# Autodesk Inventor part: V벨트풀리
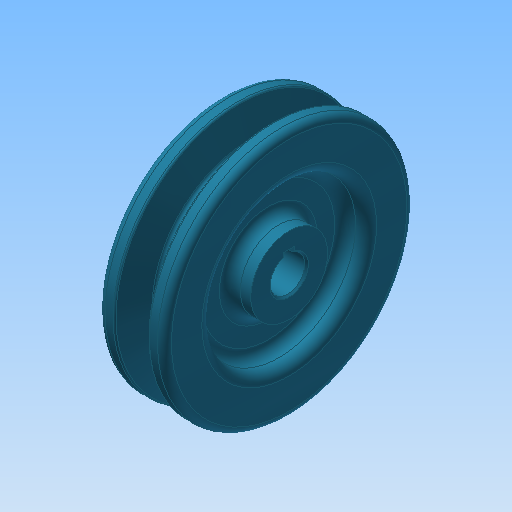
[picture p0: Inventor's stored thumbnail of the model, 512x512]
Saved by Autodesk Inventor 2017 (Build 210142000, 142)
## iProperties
Created: 2015-11
Part Number: V벨트풀리
Material: 강철, 탄소
Document SubType Name: Modeling
Designer: mduedu
Density: 7.87 g/cm^3
Mass: 380.065 g
Surface Area: 160.69 cm^2
Volume: 48.2929 cm^3
Appearance: 터키옥색
Author: mduedu
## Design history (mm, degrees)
sketch "스케치1"
  geometry: L1 (-9.5, 0)-(9.5, 0); L2 (0, 0)-(0, 35.7); L3 (-4.825, 35.7)-(-9.5, 35.7); L4 (-9.5, 35.7)-(-9.5, 0); L5 (0, 26.7)-(-2.074, 26.7); L6 (-2.074, 26.7)-(-4.825, 35.7); L7 (4.825, 35.7)-(9.5, 35.7); L8 (9.5, 35.7)-(9.5, 0); L9 (0, 26.7)-(2.074, 26.7); L10 (2.074, 26.7)-(4.825, 35.7); L11 (-9.5, 33)-(9.5, 33); 3 further points
  constraints: 22 end point, 7 point on line, 4 perpendicular, 3 symmetric about line, 1 coincident, 1 horizontal, 1 horizontal alignment, 1 midpoint, 1 vertical
  dimensions: "d0" = 19 distance of L1.start L1.end; "d2" = 71.4 diameter of L2.end L1 (derived); "d3" = 34 deg angle of L10 L6; "d4" = 6.3 distance between parallel lines of L11 L9; "d5" = 2.7 distance between parallel lines of L7 L11; "d6" = 8 distance of point (4, 33) point (-4, 33); "d7" = 66 diameter of L11 L1
revolve "회전1" sketch "스케치1" stored, may be unused: angle "d8" = 90 deg
sketch "스케치2"
  geometry: C1 r 22 at (0, 0); C2 r 11 at (0, 0); 1 further point
  constraints: 2 centre point, 2 coincident
  dimensions: "d9" = 44 diameter of C1; "d10" = 22 diameter of C2
extrude "돌출1" cut sketch "스케치2" distance "d11" = 6; taper "d12" = 0 deg
fillet "모깎기1" dims "d13" = 3
fillet "모깎기2" dims "d14" = 3
fillet "모깎기3" dims "d15" = 1, "d16" = 0.5, "d17" = 2
hole "구멍1" diameter "d20" = 10; stored, may be unused: countersink angle "d24" = 90 deg, drill point angle "d26" = 118 deg; dims "d18" = 10, "d19" = 10, "d21" = 6, "d22" = 4, "d23" = 2, "d25" = 8
sketch "스케치3"
  geometry: L1 (-1.5, 0)-(1.5, 0); L2 (1.5, 0)-(1.5, 6.4); L3 (1.5, 6.4)-(-1.5, 6.4); L4 (-1.5, 6.4)-(-1.5, 0); 2 further points
  constraints: 8 end point, 2 parallel, 1 coincident, 1 horizontal, 1 midpoint, 1 perpendicular
  dimensions: "d27" = 3 distance of L2.end L3.end; "d29" = 6.4 distance of L3.end L1.start
extrude "돌출2" cut sketch "스케치3" stored distance "d30" = 6; taper "d31" = 0 deg
chamfer "모따기1" distance "d32" = 0.5; stored, may be unused: second distance "d33" = 2, angle "d34" = 45 deg
node "솔리드1"
mirror "대칭1"
